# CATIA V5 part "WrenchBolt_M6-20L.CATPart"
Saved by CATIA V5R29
Part number: WrenchBolt_M6-20L
Bounding box of the stored display mesh (mm): x -5.11 to 5.11, y -5.11 to 5.11, z -20 to 6
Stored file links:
  C:\Users\Administrator\Desktop\프로젝트\Boxfold\WrenchBolt_M6-15L.CATPart
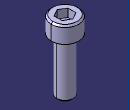
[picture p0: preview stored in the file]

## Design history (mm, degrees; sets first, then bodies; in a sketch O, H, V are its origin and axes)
Body1 (main body)
  Sketch1 on xy-plane, origin (0, 0, 0), H (1, 0, 0), V (0, 1, 0)
    circle A1 centre (0, 0) radius 5.11
    radius A1 = 5.11
  Pad1: profile Sketch1, direction (0, 0, 1), length 6
  Sketch2 on start face of Pad1, origin (0, 0, 0), H (1, 0, 0), V (0, -1, 0)
    circle A1 centre (0, 0) radius 3
    radius A1 = 3
  Pad2: profile Sketch2, direction (0, 0, -1), length 20
  Sketch3 on end face of Pad1, origin (0, 0, 6), H (1, 0, 0), V (0, 1, 0)
    point P1 (2.5475, 0)
    construction circle A1 centre (0, 0) radius 2.9416
    construction circle A2 centre (0, 0) radius 2.5475
    point P2 (2.5475, -1.4708)
    point P3 (2.5475, 1.4708)
    point P4 (0, 2.9416)
    point P5 (-2.5475, 1.4708)
    point P6 (-2.5475, -1.4708)
    point P7 (0, -2.9416)
    line L1 (2.5475, -1.4708) -> (2.5475, 1.4708)
    line L2 (2.5475, 1.4708) -> (0, 2.9416)
    line L3 (0, 2.9416) -> (-2.5475, 1.4708)
    line L4 (-2.5475, 1.4708) -> (-2.5475, -1.4708)
    line L5 (-2.5475, -1.4708) -> (0, -2.9416)
    line L6 (0, -2.9416) -> (2.5475, -1.4708)
    construction line L7 (0, 0) -> (2.5475, 0)
    radius A2 = 2.5475
    coincidence: A1 P2, A1 P3, A1 P4, A1 P5, A1 P6, A1 P7
    tangency: A2 L1, A2 L2, A2 L3, A2 L4, A2 L5, A2 L6
    midpoint: P1 L1
    horizontal: L7 H
  Pocket1: profile Sketch3, direction (0, 0, -1), length 3
  Thread1: "M6", diameter 6, depth 20, pitch 1, on face of Pad2 from Sketch2.A1, from end face of Pad2
  Chamfer1: length 0.6, angle 45, on end face of Pad2; edge [face of Pad1 from Sketch1.A1 | end face of Pad1]
  Fillet1: radius 0.25, on edge [start face of Pad1 | face of Pad2 from Sketch2.A1]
